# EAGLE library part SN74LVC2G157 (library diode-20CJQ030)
Ti's SN74LVC2G157 SINGLE 2-LINE TO 1-LINE DATA SELECTOR/MULTIPLEXER Description: This single 2-line to 1-line data selector/multiplexer is designed for 1.65-V to 5.5-V VCC operation. The SN74LVC2G157 features a common strobe (G) input. When the strobe is high, Y is low and Y is high. When the strobe is low, a single bit is selected from one of two sources and is routed to the outputs. The device provides true and complementary data. NanoStar and NanoFree package technology is a major breakthrough in IC packaging concepts, using the die as the package. This device is fully specified for partial-power-down applications using Ioff. The Ioff circuitry disables the outputs, preventing damaging current backflow through the device when it is powered down. Features: Available in the Texas Instruments NanoStar and NanoFree Packages Supports 5-V VCC Operation Inputs Accept Voltages to 5.5 V Max tpd of 6 ns at 3.3 V Low Power Consumption, 10-uA Max ICC ±24-mA Output Drive at 3.3 V Typical VOLP (Output Ground Bounce) less then 0.8 V at VCC = 3.3 V, TA = 25°C Typical VOHV (Output VOH Undershoot) greater then 2 V at VCC = 3.3 V, TA = 25°C Ioff Supports Partial-Power-Down Mode Operation Latch-Up Performance Exceeds 100 mA Per JESD 78, Class II ESD Protection Exceeds JESD 22 - 2000-V Human-Body Model (A114-A) - 1000-V Charged-Device Model (C101) Please send any comments to: messi@users.sourceforge.net
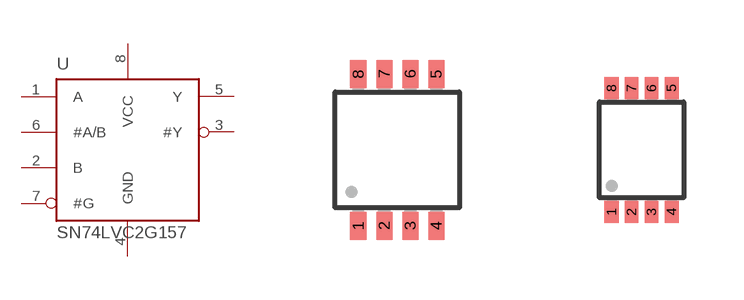
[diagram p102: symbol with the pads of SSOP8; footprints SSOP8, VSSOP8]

Designator prefix U

## SN74LVC2G157-DCT  [SSOP8]
1  A  in
2  B  in
3  #Y  out
4  GND  pwr
5  Y  out
6  #A/B  in
7  #G  in
8  VCC  pwr

## SN74LVC2G157-DCU  [VSSOP8]
Pads as for SSOP8

## Footprint SSOP8 (pad centres in mm)
smd 0.4 x 0.7: 1 -0.975,-1.9; 2 -0.325,-1.9; 3 0.325,-1.9; 4 0.975,-1.9; 5 0.975,1.9; 6 0.325,1.9; 7 -0.325,1.9; 8 -0.975,1.9

## Footprint VSSOP8 (pad centres in mm)
smd 0.35 x 0.55: 1 -0.75,-1.55; 2 -0.25,-1.55; 3 0.25,-1.55; 4 0.75,-1.55; 5 0.75,1.55; 6 0.25,1.55; 7 -0.25,1.55; 8 -0.75,1.55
